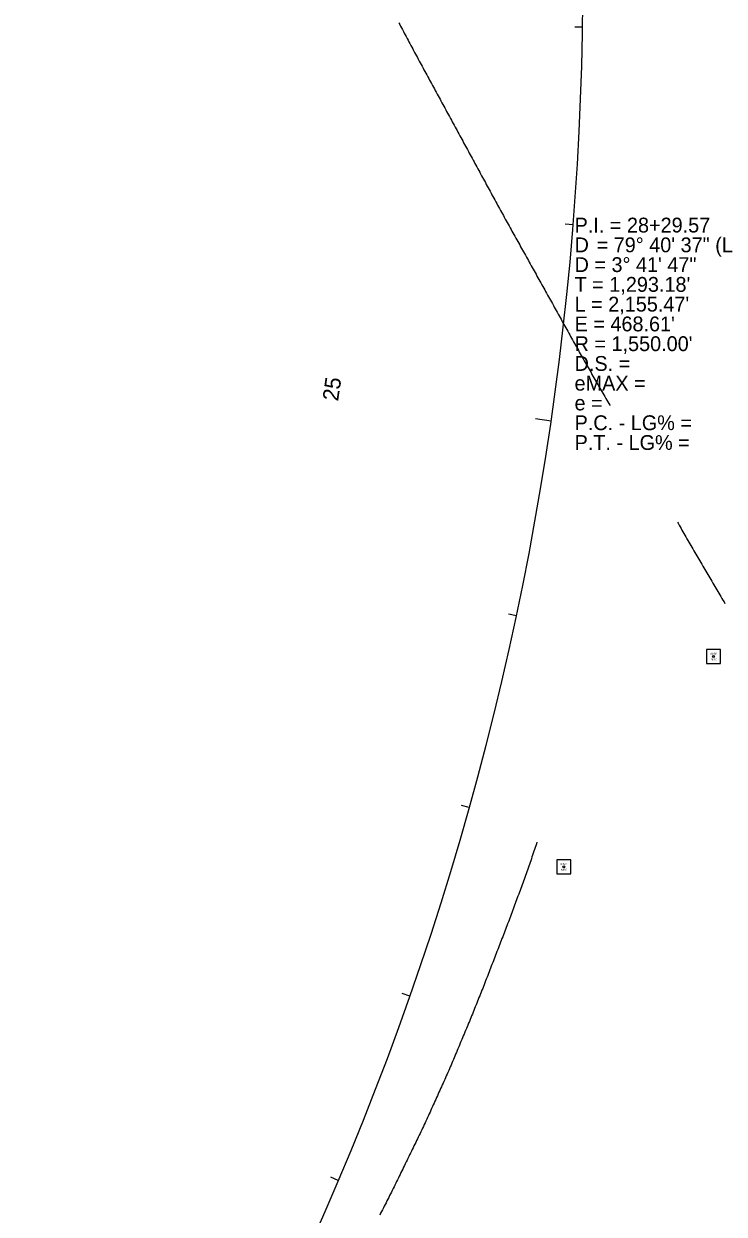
# Model space of a CAD drawing. Extents: x 205929 to 2357175, y -1785700 to 846739.
# Drawn here: x 2013480 to 2013834, y 821883 to 822486 of the extents above; entities that cross this region are included whole.
import ezdxf

# ---------------------------------------------------------------- set-up
doc = ezdxf.new("R2010")
doc.units = 0
for name, color, linetype in [('RD_HC_Cl', 7, 'Continuous'), ('RD_HC_Survey', 7, 'Continuous'), ('RD_HC_txCode', 7, 'Continuous'), ('RD_Sketch1', 7, 'Continuous'), ('RD_SMD_Locator', 7, 'Continuous')]:
    doc.layers.add(name, color=color, linetype=linetype)

msp = doc.modelspace()

# ---------------------------------------------------------------- linework, layer by layer
at = {"layer": 'RD_HC_Cl'}
for p, q in [((2013762.05, 822483.8), (2013758.05, 822483.86)), ((2013757.31, 822383.93), (2013753.32, 822384.25)), ((2013746.14, 822284.58), (2013738.22, 822285.73)), ((2013728.59, 822186.15), (2013724.68, 822186.97)), ((2013704.73, 822089.05), (2013700.88, 822090.13)), ((2013674.66, 821993.7), (2013670.89, 821995.02)), ((2013638.5, 821900.48), (2013634.82, 821902.05))]:
    msp.add_line(p, q, dxfattribs=at)
msp.add_arc((2012212.23, 822507.3), 1550, 316.11868, 35.79564, dxfattribs=at)
at = {"layer": 'RD_HC_Survey'}
for points in [[(2013831.81, 822169.03), (2013824.74, 822169.03), (2013824.74, 822161.96), (2013831.81, 822161.96)], [(2013756.07, 822062.63), (2013749, 822062.63), (2013749, 822055.56), (2013756.07, 822055.56)]]:
    msp.add_lwpolyline(points, close=True, dxfattribs=at)
for centre in [(2013828.27, 822165.49), (2013752.54, 822059.09)]:
    msp.add_circle(centre, 0.5, dxfattribs=at)
at = {"layer": 'RD_Sketch1'}
for points in [[(2013669.11, 822486.15), (2013669.58, 822485.26), (2013670.05, 822484.38), (2013670.52, 822483.5), (2013670.99, 822482.62), (2013671.46, 822481.73), (2013671.93, 822480.85), (2013672.4, 822479.97), (2013672.88, 822479.09), (2013673.35, 822478.21), (2013673.82, 822477.32), (2013674.29, 822476.44), (2013674.76, 822475.56), (2013675.23, 822474.68), (2013675.7, 822473.8), (2013676.17, 822472.91), (2013676.64, 822472.03), (2013677.11, 822471.15), (2013677.59, 822470.27), (2013678.06, 822469.39), (2013678.53, 822468.5), (2013679, 822467.62), (2013679.47, 822466.74), (2013679.94, 822465.86), (2013680.41, 822464.98), (2013680.89, 822464.1), (2013681.37, 822463.22), (2013681.85, 822462.34), (2013682.32, 822461.46), (2013682.8, 822460.59), (2013683.28, 822459.71), (2013683.76, 822458.83), (2013684.24, 822457.95), (2013684.71, 822457.07), (2013685.19, 822456.19), (2013685.67, 822455.31), (2013686.15, 822454.44), (2013686.62, 822453.56), (2013687.1, 822452.68), (2013687.58, 822451.8), (2013688.06, 822450.92), (2013688.53, 822450.04), (2013689.01, 822449.16), (2013689.49, 822448.29), (2013689.97, 822447.41), (2013690.44, 822446.53), (2013690.92, 822445.65), (2013691.4, 822444.77), (2013691.88, 822443.89), (2013692.35, 822443.02), (2013692.83, 822442.14), (2013693.31, 822441.26), (2013693.79, 822440.38), (2013694.26, 822439.5), (2013694.74, 822438.62), (2013695.22, 822437.74), (2013695.7, 822436.87), (2013696.18, 822435.99), (2013696.65, 822435.11), (2013697.13, 822434.23), (2013697.61, 822433.35), (2013698.09, 822432.47), (2013698.56, 822431.59), (2013699.04, 822430.72), (2013699.52, 822429.84), (2013700, 822428.96), (2013700.47, 822428.08), (2013700.95, 822427.2), (2013701.43, 822426.32), (2013701.91, 822425.44), (2013702.38, 822424.57), (2013702.86, 822423.69), (2013703.34, 822422.81), (2013703.82, 822421.93), (2013704.29, 822421.05), (2013704.77, 822420.17), (2013705.25, 822419.3), (2013705.73, 822418.42), (2013706.2, 822417.54), (2013706.68, 822416.66), (2013707.16, 822415.78), (2013707.64, 822414.9), (2013708.12, 822414.02), (2013708.59, 822413.15), (2013709.07, 822412.27), (2013709.55, 822411.39), (2013710.03, 822410.51), (2013710.5, 822409.63), (2013710.98, 822408.75), (2013711.46, 822407.87), (2013711.94, 822407), (2013712.41, 822406.12), (2013712.89, 822405.24), (2013713.37, 822404.36), (2013713.85, 822403.48), (2013714.32, 822402.6), (2013714.8, 822401.72), (2013715.28, 822400.85), (2013715.76, 822399.97), (2013716.23, 822399.09), (2013716.71, 822398.21), (2013717.19, 822397.33), (2013717.67, 822396.45), (2013718.14, 822395.58), (2013718.62, 822394.7), (2013719.1, 822393.82), (2013719.58, 822392.94), (2013720.06, 822392.06), (2013720.53, 822391.18), (2013721.01, 822390.31), (2013721.5, 822389.43), (2013721.99, 822388.56), (2013722.47, 822387.68), (2013722.96, 822386.81), (2013723.44, 822385.94), (2013723.93, 822385.06), (2013724.42, 822384.19), (2013724.9, 822383.32), (2013725.39, 822382.44), (2013725.88, 822381.57), (2013726.36, 822380.69), (2013726.85, 822379.82), (2013727.33, 822378.95), (2013727.82, 822378.07), (2013728.31, 822377.2), (2013728.79, 822376.33), (2013729.28, 822375.45), (2013729.76, 822374.58), (2013730.25, 822373.7), (2013730.74, 822372.83), (2013731.22, 822371.96), (2013731.71, 822371.08), (2013732.2, 822370.21), (2013732.68, 822369.34), (2013733.17, 822368.46), (2013733.65, 822367.59), (2013734.14, 822366.71), (2013734.63, 822365.84), (2013735.11, 822364.97), (2013735.6, 822364.09), (2013736.08, 822363.22), (2013736.57, 822362.35), (2013737.06, 822361.47), (2013737.54, 822360.6), (2013738.03, 822359.72), (2013738.52, 822358.85), (2013739, 822357.98), (2013739.49, 822357.1), (2013739.97, 822356.23), (2013740.46, 822355.36), (2013740.95, 822354.48), (2013741.43, 822353.61), (2013741.92, 822352.73), (2013742.41, 822351.86), (2013742.89, 822350.99), (2013743.38, 822350.11), (2013743.86, 822349.24), (2013744.35, 822348.37), (2013744.84, 822347.49), (2013745.32, 822346.62), (2013745.81, 822345.74), (2013746.29, 822344.87), (2013746.78, 822344), (2013747.27, 822343.12), (2013747.75, 822342.25), (2013748.24, 822341.38), (2013748.73, 822340.5), (2013749.21, 822339.63), (2013749.7, 822338.75), (2013750.18, 822337.88), (2013750.67, 822337.01), (2013751.16, 822336.13), (2013751.64, 822335.26), (2013752.13, 822334.38), (2013752.61, 822333.51), (2013753.1, 822332.64), (2013753.59, 822331.76), (2013754.07, 822330.89), (2013754.56, 822330.02), (2013755.05, 822329.14), (2013755.53, 822328.27), (2013756.02, 822327.39), (2013756.5, 822326.52), (2013756.99, 822325.65), (2013757.48, 822324.77), (2013757.96, 822323.9), (2013758.45, 822323.03), (2013758.94, 822322.15), (2013759.42, 822321.28), (2013759.91, 822320.4), (2013760.39, 822319.53), (2013760.88, 822318.66), (2013761.37, 822317.78), (2013761.85, 822316.91), (2013762.34, 822316.04), (2013762.82, 822315.16), (2013763.31, 822314.29), (2013763.81, 822313.42), (2013764.31, 822312.56), (2013764.81, 822311.69), (2013765.31, 822310.82), (2013765.81, 822309.96), (2013766.31, 822309.09), (2013766.81, 822308.23), (2013767.31, 822307.36), (2013767.81, 822306.49), (2013768.31, 822305.63), (2013768.81, 822304.76), (2013769.31, 822303.9), (2013769.81, 822303.03), (2013770.31, 822302.16), (2013770.81, 822301.3), (2013771.31, 822300.43), (2013771.81, 822299.57), (2013772.31, 822298.7), (2013772.81, 822297.83), (2013773.31, 822296.97), (2013773.81, 822296.1), (2013774.31, 822295.24), (2013774.81, 822294.37), (2013775.31, 822293.5), (2013775.81, 822292.64), (2013775.89, 822292.5)], [(2013810.03, 822233.38), (2013810.31, 822232.89), (2013810.81, 822232.02), (2013811.31, 822231.16), (2013811.81, 822230.29), (2013812.31, 822229.42), (2013812.81, 822228.56), (2013813.31, 822227.69), (2013813.81, 822226.83), (2013814.31, 822225.96), (2013814.81, 822225.1), (2013815.31, 822224.23), (2013815.81, 822223.36), (2013816.31, 822222.5), (2013816.81, 822221.63), (2013817.31, 822220.77), (2013817.81, 822219.9), (2013818.31, 822219.03), (2013818.81, 822218.17), (2013819.32, 822217.31), (2013819.83, 822216.44), (2013820.33, 822215.58), (2013820.84, 822214.72), (2013821.35, 822213.86), (2013821.86, 822213), (2013822.37, 822212.14), (2013822.88, 822211.28), (2013823.38, 822210.42), (2013823.89, 822209.55), (2013824.4, 822208.69), (2013824.91, 822207.83), (2013825.42, 822206.97), (2013825.92, 822206.11), (2013826.43, 822205.25), (2013826.94, 822204.39), (2013827.45, 822203.53), (2013827.96, 822202.67), (2013828.47, 822201.8), (2013828.97, 822200.94), (2013829.48, 822200.08), (2013829.99, 822199.22), (2013830.5, 822198.36), (2013831.01, 822197.5), (2013831.51, 822196.64), (2013832.02, 822195.78), (2013832.53, 822194.91), (2013833.04, 822194.05), (2013833.55, 822193.19), (2013834.05, 822192.33)], [(2013738.97, 822071.61), (2013738.68, 822070.72), (2013738.36, 822069.77), (2013738.05, 822068.82), (2013737.73, 822067.87), (2013737.42, 822066.93), (2013737.1, 822065.98), (2013736.78, 822065.03), (2013736.47, 822064.08), (2013736.15, 822063.13), (2013735.84, 822062.18), (2013735.52, 822061.23), (2013735.2, 822060.28), (2013734.89, 822059.34), (2013734.57, 822058.39), (2013734.23, 822057.45), (2013733.88, 822056.51), (2013733.54, 822055.57), (2013733.19, 822054.63), (2013732.85, 822053.69), (2013732.5, 822052.76), (2013732.16, 822051.82), (2013731.81, 822050.88), (2013731.46, 822049.94), (2013731.12, 822049), (2013730.77, 822048.06), (2013730.43, 822047.13), (2013730.08, 822046.19), (2013729.74, 822045.25), (2013729.39, 822044.31), (2013729.04, 822043.37), (2013728.7, 822042.43), (2013728.35, 822041.5), (2013728.01, 822040.56), (2013727.66, 822039.62), (2013727.32, 822038.68), (2013726.97, 822037.74), (2013726.62, 822036.8), (2013726.28, 822035.87), (2013725.93, 822034.93), (2013725.59, 822033.99), (2013725.24, 822033.05), (2013724.89, 822032.12), (2013724.53, 822031.18), (2013724.17, 822030.25), (2013723.81, 822029.32), (2013723.45, 822028.38), (2013723.09, 822027.45), (2013722.73, 822026.52), (2013722.37, 822025.58), (2013722.01, 822024.65), (2013721.65, 822023.72), (2013721.29, 822022.79), (2013720.93, 822021.85), (2013720.57, 822020.92), (2013720.21, 822019.99), (2013719.85, 822019.05), (2013719.49, 822018.12), (2013719.13, 822017.19), (2013718.77, 822016.25), (2013718.41, 822015.32), (2013718.05, 822014.39), (2013717.69, 822013.46), (2013717.33, 822012.52), (2013716.97, 822011.59), (2013716.61, 822010.66), (2013716.25, 822009.72), (2013715.89, 822008.79), (2013715.53, 822007.86), (2013715.17, 822006.92), (2013714.81, 822005.99), (2013714.45, 822005.06), (2013714.09, 822004.13), (2013713.73, 822003.19), (2013713.37, 822002.26), (2013713.01, 822001.33), (2013712.65, 822000.39), (2013712.28, 821999.47), (2013711.91, 821998.54), (2013711.54, 821997.61), (2013711.17, 821996.68), (2013710.79, 821995.75), (2013710.42, 821994.82), (2013710.05, 821993.9), (2013709.68, 821992.97), (2013709.31, 821992.04), (2013708.94, 821991.11), (2013708.57, 821990.18), (2013708.2, 821989.25), (2013707.82, 821988.32), (2013707.45, 821987.4), (2013707.08, 821986.47), (2013706.71, 821985.54), (2013706.34, 821984.61), (2013705.97, 821983.68), (2013705.59, 821982.76), (2013705.21, 821981.83), (2013704.82, 821980.91), (2013704.43, 821979.99), (2013704.05, 821979.06), (2013703.66, 821978.14), (2013703.28, 821977.22), (2013702.89, 821976.3), (2013702.51, 821975.37), (2013702.12, 821974.45), (2013701.74, 821973.53), (2013701.35, 821972.61), (2013700.97, 821971.68), (2013700.58, 821970.76), (2013700.19, 821969.84), (2013699.81, 821968.92), (2013699.42, 821967.99), (2013699.04, 821967.07), (2013698.65, 821966.15), (2013698.27, 821965.22), (2013697.88, 821964.3), (2013697.5, 821963.38), (2013697.11, 821962.46), (2013696.73, 821961.53), (2013696.34, 821960.61), (2013695.95, 821959.69), (2013695.57, 821958.77), (2013695.18, 821957.84), (2013694.8, 821956.92), (2013694.39, 821956.01), (2013693.98, 821955.09), (2013693.57, 821954.18), (2013693.16, 821953.27), (2013692.75, 821952.36), (2013692.34, 821951.45), (2013691.92, 821950.54), (2013691.51, 821949.63), (2013691.1, 821948.72), (2013690.69, 821947.8), (2013690.28, 821946.89), (2013689.86, 821945.98), (2013689.45, 821945.07), (2013689.04, 821944.16), (2013688.63, 821943.25), (2013688.22, 821942.34), (2013687.81, 821941.43), (2013687.39, 821940.51), (2013686.98, 821939.6), (2013686.57, 821938.69), (2013686.16, 821937.78), (2013685.75, 821936.87), (2013685.33, 821935.96), (2013684.92, 821935.05), (2013684.51, 821934.14), (2013684.1, 821933.22), (2013683.69, 821932.31), (2013683.28, 821931.4), (2013682.86, 821930.49), (2013682.45, 821929.58), (2013682.04, 821928.67), (2013681.61, 821927.77), (2013681.17, 821926.87), (2013680.73, 821925.97), (2013680.3, 821925.07), (2013679.86, 821924.17), (2013679.42, 821923.27), (2013678.98, 821922.37), (2013678.54, 821921.47), (2013678.11, 821920.57), (2013677.67, 821919.67), (2013677.23, 821918.78), (2013676.79, 821917.88), (2013676.36, 821916.98), (2013675.92, 821916.08), (2013675.48, 821915.18), (2013675.04, 821914.28), (2013674.6, 821913.38), (2013674.17, 821912.48), (2013673.73, 821911.58), (2013673.29, 821910.68), (2013672.85, 821909.79), (2013672.41, 821908.89), (2013671.98, 821907.99), (2013671.54, 821907.09), (2013671.1, 821906.19), (2013670.66, 821905.29), (2013670.23, 821904.39), (2013669.79, 821903.49), (2013669.35, 821902.59), (2013668.91, 821901.69), (2013668.47, 821900.8), (2013668.04, 821899.9), (2013667.6, 821899), (2013667.16, 821898.1), (2013666.72, 821897.2), (2013666.28, 821896.3), (2013665.84, 821895.41), (2013665.39, 821894.51), (2013664.93, 821893.62), (2013664.48, 821892.73), (2013664.03, 821891.84), (2013663.58, 821890.95), (2013663.13, 821890.05), (2013662.67, 821889.16), (2013662.22, 821888.27), (2013661.77, 821887.38), (2013661.32, 821886.49), (2013660.87, 821885.59), (2013660.41, 821884.7), (2013659.96, 821883.81), (2013659.51, 821882.92)]]:
    msp.add_lwpolyline(points, dxfattribs=at)
at = {"layer": 'RD_SMD_Locator'}
for centre in [(2013828.27, 822165.49), (2013752.54, 822059.09)]:
    msp.add_circle(centre, 0.001, dxfattribs=at)

# ---------------------------------------------------------------- texts
at = {"layer": 'RD_HC_Cl'}
for s, p in [('P.I. = 28+29.57', (2013758, 822380)), ('D', (2013758, 822370)), ('    = 79%%d 40\' 37" (LT)', (2013758, 822370)), ('D = 3%%d 41\' 47"', (2013758, 822360)), ("T = 1,293.18'", (2013758, 822350)), ("L = 2,155.47'", (2013758, 822340)), ("E = 468.61'", (2013758, 822330)), ("R = 1,550.00'", (2013758, 822320)), ('D.S. = ', (2013758, 822310)), ('eMAX = ', (2013758, 822300)), ('e = ', (2013758, 822290)), ('P.C. - LG% = ', (2013758, 822280)), ('P.T. - LG% = ', (2013758, 822270))]:
    msp.add_text(s, height=7.5, dxfattribs=at).set_placement(p)
msp.add_text('25', height=8, rotation=81.73834, dxfattribs=at).set_placement((2013638.43, 822294.4))
at = {"layer": 'RD_HC_txCode'}
for s, p in [('8548', (2013826.64, 822166.49)), ('MSC', (2013826.96, 822163.49)), ('8356', (2013750.89, 822060.09)), ('MSC', (2013751.22, 822057.09))]:
    msp.add_text(s, height=1, dxfattribs=at).set_placement(p)

doc.saveas('drawing.dxf')
